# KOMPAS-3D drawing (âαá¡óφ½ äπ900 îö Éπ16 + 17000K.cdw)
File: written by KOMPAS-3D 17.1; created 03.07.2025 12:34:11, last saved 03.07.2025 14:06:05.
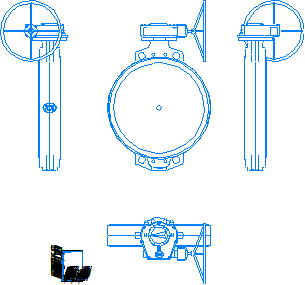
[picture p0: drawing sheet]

Sheet 1: A4, portrait

Title block, sheet 1: sheets: 1; sheet format: A4; stored path: \\adlc.lan\data\АДЛ_ПКД\3D-модели\ADL production\Дисковые поворотные затворы ГРАНВЭЛ\межфланцевый с китайским редуктором Ру16\KOMPAS 2D\Гранвэл Ду900 МФ Ру16 + 17000K.cdw

Views: Вид 1, Спереди, Проекционный вид 2, Проекционный вид 3, Проекционный вид 4
Referenced files in \\adlc.lan\data\АДЛ_ПКД\3D-модели\ADL production\Дисковые поворотные затворы ГРАНВЭЛ\межфланцевый с китайским редуктором Ру16\KOMPAS 3D\: Гранвэл Ду900 МФ Ру16 + 17000K.m3d
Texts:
  Andrey
  АДЛ
Dimensions and other numbers on the sheet: 1:1; 1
